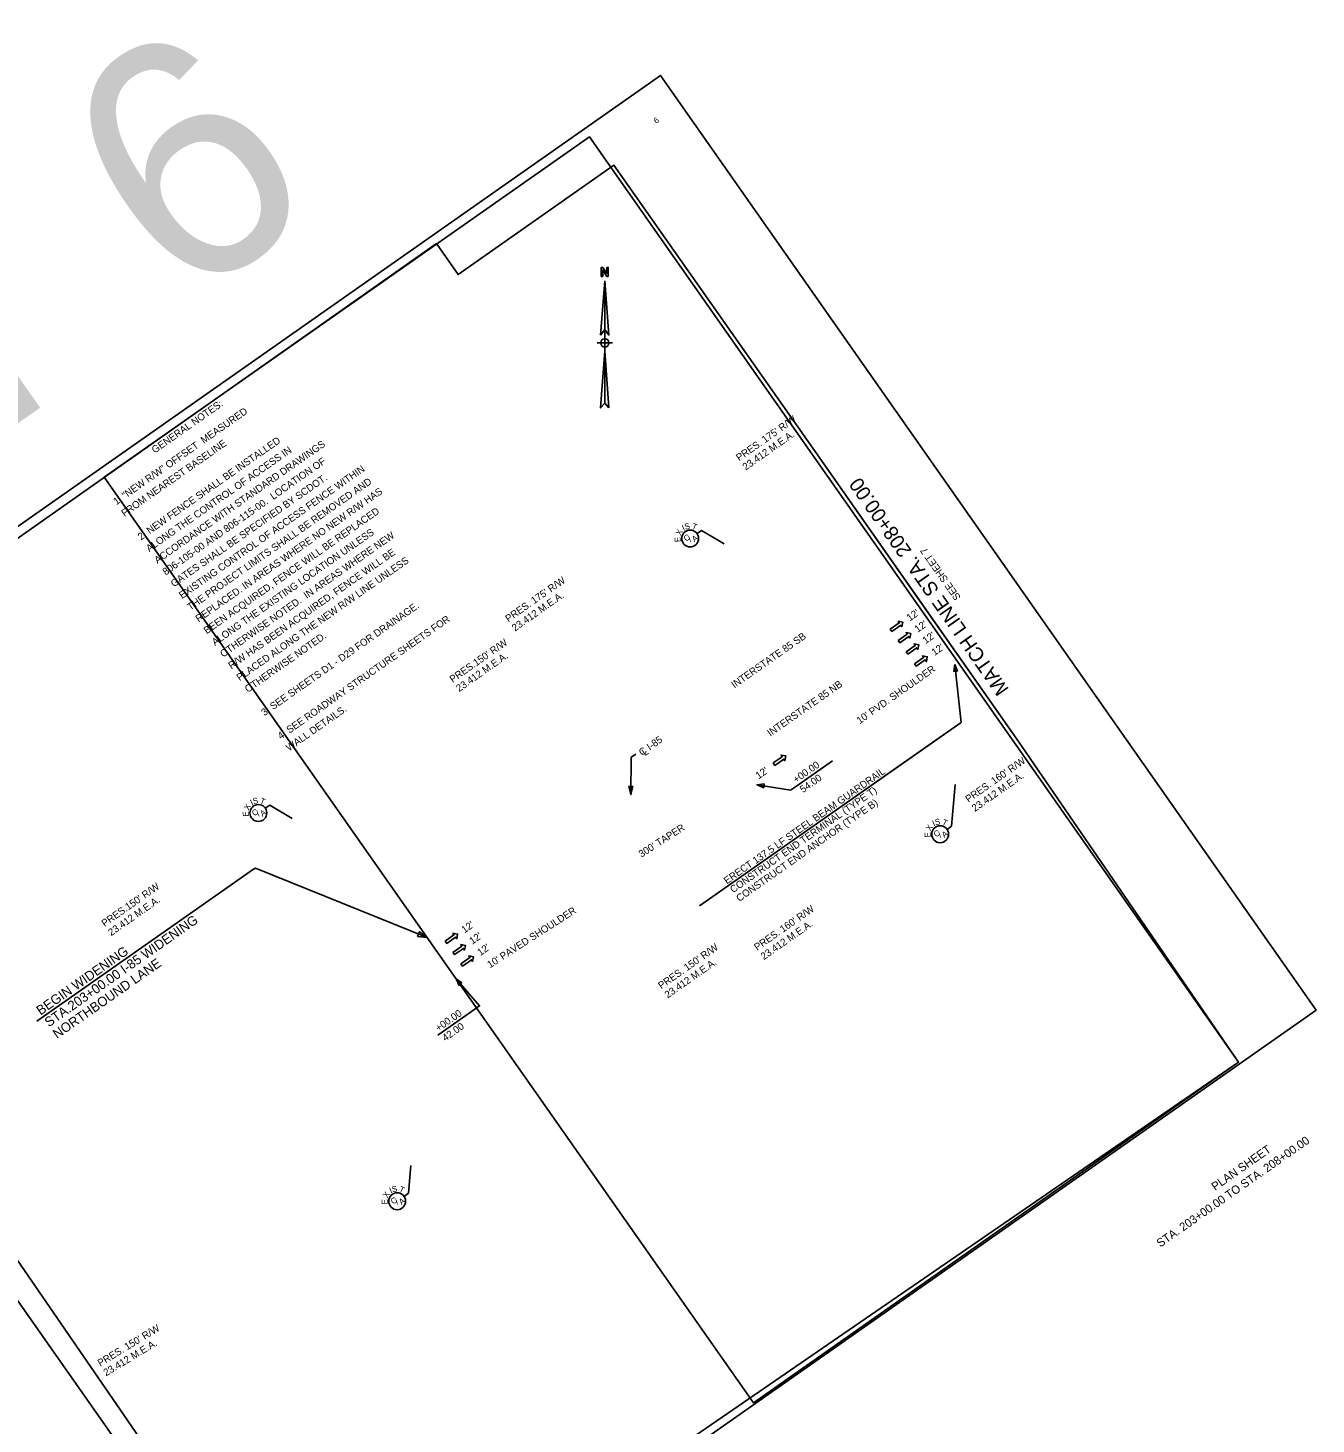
# Model space of a CAD drawing. Extents: x 1602507 to 1604427, y 1087817 to 1089602.
# Drawn here: x 1603348 to 1604427, y 1088432 to 1089602 of the extents above; entities that cross this region are included whole.
import ezdxf

# ---------------------------------------------------------------- set-up
doc = ezdxf.new("R2010")
doc.units = 0
for name, color, linetype in [('C_G_Sho', 7, 'Continuous'), ('EOP', 7, 'Continuous'), ('RD_DTM_BkLn1', 7, 'Continuous'), ('RD_EX_Bridge', 7, 'Continuous'), ('RD_EX_Driveway', 7, 'Continuous'), ('RD_EX_Fence_Other', 7, 'Continuous'), ('RD_EX_H2O_WetLd', 7, 'Continuous'), ('RD_EX_Misc', 7, 'Continuous'), ('RD_EX_Misc_Golf_Teebox', 7, 'Continuous'), ('RD_EX_Road', 7, 'Continuous'), ('RD_EX_VEG', 7, 'Continuous'), ('RD_HC_SUR_Distance_TX400', 7, 'Continuous')]:
    doc.layers.add(name, color=color, linetype=linetype)

msp = doc.modelspace()

# ---------------------------------------------------------------- linework, layer by layer
at = {"layer": 'EOP'}
msp.add_line((1604117.1, 1089011.1), (1603910.7, 1088866.3), dxfattribs=at)
msp.add_lwpolyline([(1603910.7, 1088866.3), (1604129.8, 1089020), (1604124.7, 1089068.5)], dxfattribs=at)
msp.add_lwpolyline([(1604126.9, 1089062.9), (1604124.7, 1089068.5), (1604123.8, 1089062.6)], close=True, dxfattribs=at)
at = {"layer": 'RD_DTM_BkLn1'}
for p, q in [((1603853.5, 1088990.8), (1603857.4, 1088993.5)), ((1603853.1, 1088959.5), (1603853.5, 1088990.8))]:
    msp.add_line(p, q, dxfattribs=at)
msp.add_lwpolyline([(1603854.9, 1088966.4), (1603851.5, 1088966.4), (1603853.1, 1088959.5)], close=True, dxfattribs=at)
at = {"layer": 'RD_EX_Bridge'}
for points in [[(1604070.5, 1089098.1), (1604071.9, 1089096.2), (1604079.4, 1089101.4), (1604080.3, 1089100.1), (1604081, 1089104), (1604077.1, 1089104.7), (1604078, 1089103.4)], [(1604077.1, 1089088.7), (1604078.5, 1089086.7), (1604086, 1089092), (1604086.9, 1089090.7), (1604087.6, 1089094.6), (1604083.7, 1089095.3), (1604084.6, 1089094)], [(1604083.8, 1089079.2), (1604085.2, 1089077.2), (1604092.7, 1089082.5), (1604093.6, 1089081.1), (1604094.3, 1089085.1), (1604090.4, 1089085.8), (1604091.3, 1089084.4)], [(1604090.9, 1089069.1), (1604092.2, 1089067.1), (1604099.8, 1089072.4), (1604100.7, 1089071), (1604101.4, 1089075), (1604097.4, 1089075.7), (1604098.4, 1089074.3)], [(1603972.4, 1088986), (1603973.8, 1088984), (1603981.3, 1088989.3), (1603982.2, 1088987.9), (1603982.9, 1088991.9), (1603979, 1088992.6), (1603979.9, 1088991.2)], [(1603697.4, 1088836.8), (1603698.8, 1088834.8), (1603706.3, 1088840), (1603707.2, 1088838.7), (1603707.9, 1088842.7), (1603704, 1088843.3), (1603704.9, 1088842)], [(1603704, 1088827.3), (1603705.4, 1088825.4), (1603712.9, 1088830.6), (1603713.8, 1088829.3), (1603714.5, 1088833.2), (1603710.6, 1088833.9), (1603711.5, 1088832.6)], [(1603710.7, 1088817.8), (1603712.1, 1088815.8), (1603719.6, 1088821.1), (1603720.5, 1088819.7), (1603721.2, 1088823.7), (1603717.3, 1088824.4), (1603718.2, 1088823)]]:
    msp.add_lwpolyline(points, close=True, dxfattribs=at)
at = {"layer": 'RD_EX_Driveway'}
for points in [[(1603411.8, 1089225.4), (1603818.5, 1089510.6), (1604362.4, 1088735.2), (1603955.8, 1088449.9)], [(1603411.8, 1089225.4), (1603818.5, 1089510.6), (1604362.4, 1088735.2), (1603955.8, 1088449.9)], [(1604005.5, 1089249.7), (1604177.8, 1089004.1), (1604362.4, 1088735.2), (1603589.9, 1088204.3), (1603058.7, 1088977), (1603690.3, 1089421.2), (1603708.4, 1089395.3), (1603838.9, 1089487)]]:
    msp.add_lwpolyline(points, close=True, dxfattribs=at)
at = {"layer": 'RD_EX_Fence_Other'}
msp.add_lwpolyline([(1602506.7, 1088600.2), (1603878, 1089562.1), (1604427.3, 1088779), (1603056, 1087817.2)], close=True, dxfattribs=at)
at = {"layer": 'RD_EX_Misc_Golf_Teebox'}
for p, q in [((1604022, 1088987.7), (1603991.1, 1088966.1)), ((1603536.8, 1088896.9), (1603355.5, 1088769.8)), ((1603722.3, 1088779.6), (1603691.4, 1088757.9))]:
    msp.add_line(p, q, dxfattribs=at)
for points in [[(1603964.9, 1088968.4), (1603958.9, 1088967.8), (1603964.4, 1088965.3)], [(1603051.3, 1087942.4), (1603523.1, 1088273.3), (1603076.7, 1088909.7), (1602605, 1088578.8)], [(1603674.4, 1088840.7), (1603682.3, 1088839.8), (1603675.9, 1088844.6)], [(1603711.6, 1088801.8), (1603706.6, 1088805.1), (1603709.2, 1088799.7)]]:
    msp.add_lwpolyline(points, close=True, dxfattribs=at)
for points in [[(1603991.1, 1088966.1), (1603986.9, 1088963.1), (1603958.9, 1088967.8)], [(1603536.8, 1088896.9), (1603538.7, 1088897.8), (1603682.3, 1088839.8)], [(1603722.3, 1088779.6), (1603726.3, 1088782.4), (1603706.6, 1088805.1)]]:
    msp.add_lwpolyline(points, dxfattribs=at)
at = {"layer": 'RD_EX_Road'}
for p, q in [((1603831.2, 1089389.9), (1603827.8, 1089344.6)), ((1603831.2, 1089349.2), (1603827.8, 1089344.6)), ((1603831.2, 1089349.2), (1603831.2, 1089331.4)), ((1603837.8, 1089338), (1603824.8, 1089338)), ((1603831.2, 1089331.4), (1603834.7, 1089283.5)), ((1603834.7, 1089283.5), (1603831.2, 1089287.4))]:
    msp.add_line(p, q, dxfattribs=at)
msp.add_lwpolyline([(1603834.2, 1089393.7), (1603833, 1089393.7), (1603829.5, 1089399.2), (1603829.5, 1089398.4), (1603829.5, 1089393.7), (1603828.3, 1089393.7), (1603828.3, 1089401.3), (1603829.5, 1089401.3), (1603833, 1089396.2), (1603833, 1089396.7), (1603833, 1089401.3), (1603834.2, 1089401.3), (1603834.2, 1089393.7)], dxfattribs=at)
for points in [[(1603831.2, 1089389.9), (1603834.7, 1089344.6), (1603831.2, 1089349.2)], [(1603831.2, 1089331.4), (1603831.2, 1089287.4), (1603827.8, 1089283.5)]]:
    msp.add_lwpolyline(points, close=True, dxfattribs=at)
msp.add_circle((1603831.3, 1089338), 3.45, dxfattribs=at)
at = {"layer": 'RD_EX_VEG'}
msp.add_lwpolyline([(1604177.8, 1089004.1), (1604091.7, 1089126.9), (1604005.5, 1089249.7)], dxfattribs=at)
at = {"layer": 'RD_HC_SUR_Distance_TX400'}
for p, q in [((1603908.6, 1089178.2), (1603912.4, 1089180.8)), ((1603912.4, 1089180.8), (1603931.2, 1089169.6)), ((1604121.8, 1088933), (1604124.8, 1088968.1)), ((1603546.8, 1088948.1), (1603550.6, 1088950.8)), ((1603550.6, 1088950.8), (1603569.3, 1088939.6)), ((1604118.1, 1088930.4), (1604121.8, 1088933)), ((1603666.9, 1088625.5), (1603668.8, 1088648.7)), ((1603663.1, 1088622.8), (1603666.9, 1088625.5))]:
    msp.add_line(p, q, dxfattribs=at)
for centre in [(1603902.8, 1089174.1), (1603541, 1088944.1), (1604112.3, 1088926.3), (1603657.3, 1088618.8)]:
    msp.add_circle(centre, 7.08, dxfattribs=at)

# ---------------------------------------------------------------- texts
at = {"layer": 'C_G_Sho'}
for s, p in [('GENERAL NOTES: ', (1603454.2, 1089245.2)), ('1. "NEW R/W" OFFSET  MEASURED ', (1603422, 1089201.9)), ('FROM NEAREST BASELINE', (1603428.8, 1089192.1)), ('2. NEW FENCE SHALL BE INSTALLED', (1603442.6, 1089172.4)), ('ALONG THE CONTROL OF ACCESS IN ', (1603449.5, 1089162.6)), ('ACCORDANCE WITH STANDARD DRAWINGS ', (1603456.4, 1089152.8)), ('806-105-00 AND 806-115-00.  LOCATION OF ', (1603463.3, 1089143)), ('EXISTING CONTROL OF ACCESS FENCE WITHIN ', (1603477.1, 1089123.3)), ('GATES SHALL BE SPECIFIED BY SCDOT.  ', (1603470.2, 1089133.1)), ('THE PROJECT LIMITS SHALL BE REMOVED AND ', (1603484, 1089113.5)), ('REPLACED. IN AREAS WHERE NO NEW R/W HAS ', (1603490.9, 1089103.7)), ('BEEN ACQUIRED, FENCE WILL BE REPLACED ', (1603497.8, 1089093.8)), ('ALONG THE EXISTING LOCATION UNLESS ', (1603504.6, 1089084)), ('OTHERWISE NOTED.  IN AREAS WHERE NEW ', (1603511.5, 1089074.2)), ('R/W HAS BEEN ACQUIRED, FENCE WILL BE ', (1603518.4, 1089064.4)), ('PLACED ALONG THE NEW R/W LINE UNLESS ', (1603525.3, 1089054.5)), ('3. SEE SHEETS D1 - D29 FOR DRAINAGE.', (1603546, 1089025.1)), ('4. SEE ROADWAY STRUCTURE SHEETS FOR ', (1603559.8, 1089005.4)), ('OTHERWISE NOTED.', (1603532.2, 1089044.7)), ('WALL DETAILS.', (1603566.7, 1088995.6))]:
    msp.add_text(s, height=6, rotation=35.0452, dxfattribs=at).set_placement(p)
at = {"layer": 'EOP'}
for s, p in [('ERECT 137.5 LF STEEL BEAM GUARDRAIL', (1603933.6, 1088884.2)), ('CONSTRUCT END TERMINAL (TYPE T)', (1603938.8, 1088876.8)), ('CONSTRUCT END ANCHOR (TYPE B)', (1603944, 1088869.5))]:
    msp.add_text(s, height=6, rotation=35.0485, dxfattribs=at).set_placement(p)
at = {"layer": 'RD_DTM_BkLn1'}
for s, height, rotation, p in [('INTERSTATE 85 SB', 6, 35.0535, (1603939.9, 1089048.4)), ('INTERSTATE 85 NB', 6, 35.0535, (1603970, 1089008)), ('C I-85', 6, 35.0535, (1603862.4, 1088991.7)), ('L', 6, 35.0535, (1603864.9, 1088991.6)), ('STA. 203+00.00 TO STA. 208+00.00', 6.983, 35.0468, (1604296.7, 1088579.9)), ('PLAN SHEET', 6.98, 35.0468, (1604342.7, 1088627.3))]:
    msp.add_text(s, height=height, rotation=rotation, dxfattribs=at).set_placement(p)
at = {"layer": 'RD_EX_H2O_WetLd'}
msp.add_text('SHEET 6', height=200, rotation=35.0468, dxfattribs=at).set_placement((1602684.9, 1088811.5))
at = {"layer": 'RD_EX_Misc'}
for s, rotation, p in [("PRES. 175' R/W", 35.0468, (1603943.9, 1089238.7)), ('23.412 M.E.A.', 35.0468, (1603949.3, 1089230.9)), ("PRES. 175' R/W", 35.0468, (1603750.5, 1089103.8)), ('23.412 M.E.A.', 35.0468, (1603756, 1089096)), ("PRES.150' R/W", 35.0468, (1603703.8, 1089053)), ('23.412 M.E.A.', 35.0468, (1603709.2, 1089045.3)), ("PRES. 160' R/W", 35.0468, (1604136, 1088952.6)), ('23.412 M.E.A.', 35.0468, (1604141.4, 1088944.9)), ("PRES.150' R/W", 35.0468, (1603412.2, 1088848.5)), ('23.412 M.E.A.', 35.0468, (1603417.7, 1088840.8)), ("PRES. 160' R/W", 35.0468, (1603959, 1088828.5)), ('23.412 M.E.A.', 35.0468, (1603964.5, 1088820.7)), ("PRES. 150' R/W", 35.0468, (1603878.6, 1088796.3)), ('23.412 M.E.A.', 35.0468, (1603884, 1088788.6)), ("PRES. 150' R/W", 31.2587, (1603408.5, 1088480.1)), ('23.412 M.E.A.', 31.2587, (1603413.4, 1088472))]:
    msp.add_text(s, height=6, rotation=rotation, dxfattribs=at).set_placement(p)
at = {"layer": 'RD_EX_Misc_Golf_Teebox'}
for s, height, rotation, p in [('6', 5, 35.0468, (1603874.3, 1089521.3)), ("12'", 6, 35.0468, (1604086.8, 1089104.5)), ("12'", 6, 35.0468, (1604093.4, 1089095)), ("12'", 6, 35.0468, (1604100.1, 1089085.5)), ("12'", 6, 35.0468, (1604107.6, 1089075.6)), ("10' PVD. SHOULDER", 6, 35.2022, (1604044.9, 1089018.4)), ("12'", 6, 35.0468, (1603960.2, 1088972.2)), ('+00.00', 6, 35.0468, (1603991.6, 1088968.9)), ('54.00', 6, 35.0468, (1603997.3, 1088960.7)), ("300' TAPER", 6, 32.7562, (1603862, 1088906.6)), ("10' PAVED SHOULDER", 6, 32.814, (1603735.1, 1088813.9)), ('STA.203+00.00 I-85 WIDENING', 8, 35.0485, (1603365.4, 1088764.4)), ("12'", 6, 35.0468, (1603713.7, 1088843.1)), ("12'", 6, 35.0468, (1603720.3, 1088833.7)), ('BEGIN WIDENING', 8, 35.0485, (1603358.5, 1088774.3)), ("12'", 6, 35.0468, (1603727, 1088824.1)), ('NORTHBOUND LANE', 8, 35.0485, (1603372.3, 1088754.6)), ('+00.00', 6, 35.0468, (1603691.9, 1088760.7)), ('42.00', 6, 35.0468, (1603697.6, 1088752.5))]:
    msp.add_text(s, height=height, rotation=rotation, dxfattribs=at).set_placement(p)
at = {"layer": 'RD_EX_VEG'}
for s, height, rotation, p in [('MATCH LINE STA. 208+00.00', 12, 125.0468, (1604170.3, 1089047.8)), ('SEE SHEET 7', 6, 125.0981, (1604129.8, 1089124.9))]:
    msp.add_text(s, height=height, rotation=rotation, dxfattribs=at).set_placement(p)
at = {"layer": 'RD_HC_SUR_Distance_TX400'}
for s, rotation, p in [('X', 60.1403, (1603894.7, 1089176.1)), ('I', 24.9789, (1603897.3, 1089180.4)), ('S', 13.2584, (1603898.7, 1089181.4)), ('T', 338.0969, (1603903.7, 1089182.5)), ('E', 93.6275, (1603894.9, 1089171.2)), ('C', 35.0436, (1603899.5, 1089171.3)), ('/', 35.0436, (1603903.1, 1089171.2)), ('A', 35.0436, (1603906.3, 1089170.8)), ('X', 60.1403, (1603532.8, 1088946)), ('I', 24.9789, (1603535.5, 1088950.4)), ('C', 35.0436, (1603537.7, 1088941.2)), ('S', 13.2584, (1603536.9, 1088951.4)), ('T', 338.0969, (1603541.8, 1088952.4)), ('E', 93.6275, (1603533.1, 1088941.2)), ('/', 35.0436, (1603541.3, 1088941.2)), ('A', 35.0436, (1603544.5, 1088940.8)), ('I', 23.0267, (1604106.9, 1088932.8)), ('S', 11.3062, (1604108.4, 1088933.8)), ('T', 336.1448, (1604113.4, 1088934.6)), ('E', 91.6753, (1604104.3, 1088923.7)), ('X', 58.1882, (1604104.1, 1088928.6)), ('C', 35.0436, (1604108.9, 1088923.5)), ('/', 35.0436, (1604112.6, 1088923.4)), ('A', 35.0436, (1604115.7, 1088923)), ('S', 11.3062, (1603653.4, 1088626.2)), ('T', 336.1448, (1603658.4, 1088627.1)), ('E', 91.6753, (1603649.3, 1088616.2)), ('X', 58.1882, (1603649.2, 1088621)), ('I', 23.0267, (1603652, 1088625.3)), ('C', 35.0436, (1603654, 1088615.9)), ('/', 35.0436, (1603657.6, 1088615.9)), ('A', 35.0436, (1603660.8, 1088615.5))]:
    msp.add_text(s, height=5, rotation=rotation, dxfattribs=at).set_placement(p)

doc.saveas('drawing.dxf')
